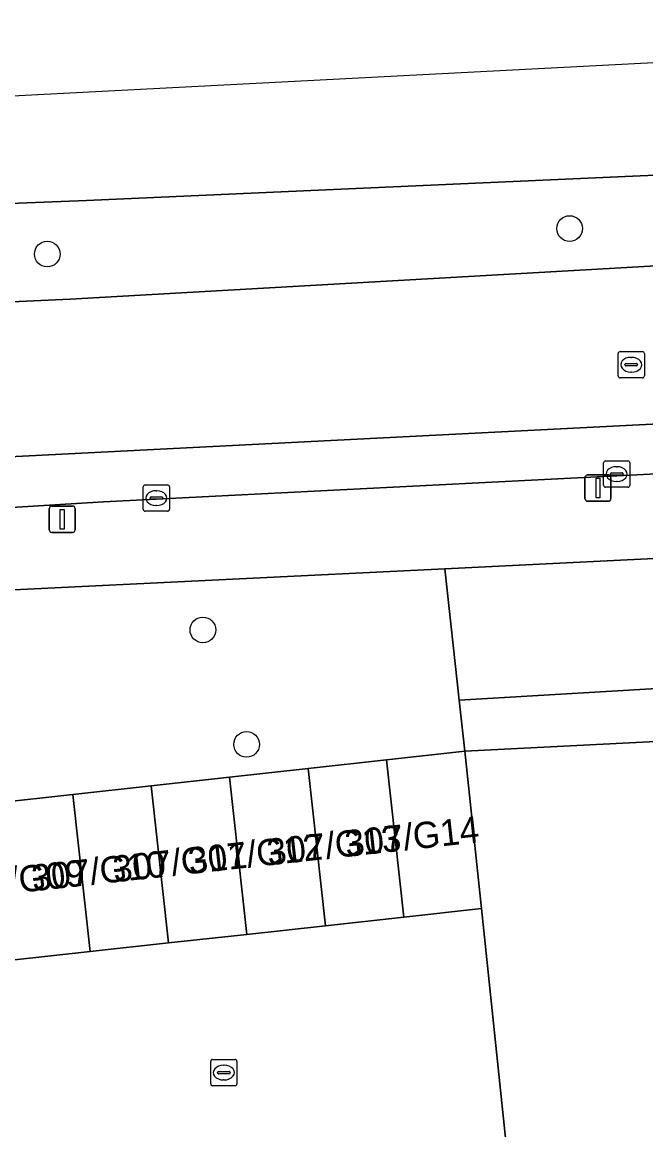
# Model space of a CAD drawing. Extents: x 161248 to 161848, y 384871 to 385383.
# Drawn here: x 161322.33 to 161346.09, y 385315.39 to 385357.57 of the extents above; entities that cross this region are included whole.
import ezdxf

# ---------------------------------------------------------------- set-up
doc = ezdxf.new("R2010")
doc.units = 0
for name, color, linetype in [('IMGEO_Berm_groen', 7, 'Continuous'), ('IMGEO_Boom', 7, 'Continuous'), ('IMGEO_Erf', 7, 'Continuous'), ('IMGEO_Groenvoorziening', 7, 'Continuous'), ('IMGEO_Kolk', 7, 'Continuous'), ('IMGEO_Lichtmast', 7, 'Continuous'), ('IMGEO_Pand', 7, 'Continuous'), ('IMGEO_Pand_nummerreeks', 7, 'Continuous'), ('IMGEO_Rijbaan_lokaal_gesloten', 7, 'Continuous'), ('IMGEO_Rijbaan_lokaal_open', 7, 'Continuous'), ('IMGEO_Rioolput', 7, 'Continuous'), ('IMGEO_Voetpad_open', 7, 'Continuous')]:
    doc.layers.add(name, color=color, linetype=linetype)

msp = doc.modelspace()

# ---------------------------------------------------------------- linework, layer by layer
at = {"layer": 'IMGEO_Berm_groen'}
for points in [[(161268.516, 385344.454), (161288.559, 385345.391), (161324.155, 385347.024), (161376.6, 385350.004), (161376.38, 385354.718), (161376.236, 385357.567), (161370.581, 385357.274)], [(161358.872, 385352.316), (161355.845, 385352.165), (161324.775, 385350.775), (161310.535, 385350.215), (161285.7, 385348.87), (161268.134, 385347.902)]]:
    msp.add_lwpolyline(points, dxfattribs=at)
at = {"layer": 'IMGEO_Boom'}
for centre in [(161343.184, 385349.709), (161323.285, 385348.736), (161329.214, 385334.424), (161330.878, 385330.066)]:
    msp.add_circle(centre, 0.489, dxfattribs=at)
at = {"layer": 'IMGEO_Erf'}
msp.add_lwpolyline([(161363.214, 385333.159), (161361.151, 385333.056), (161338.98, 385331.746), (161339.195, 385329.807), (161363.523, 385331.042), (161363.758, 385326.266), (161365.156, 385326.33), (161365.668, 385316.057), (161364.248, 385315.991)], dxfattribs=at)
at = {"layer": 'IMGEO_Groenvoorziening'}
msp.add_lwpolyline([(161377.566, 385338.678), (161338.425, 385336.75), (161338.98, 385331.746), (161361.151, 385333.056), (161363.214, 385333.159), (161369.13, 385333.454), (161375.009, 385333.746), (161381.942, 385316.048), (161382.867, 385316.429)], close=True, dxfattribs=at)
for points in [[(161338.98, 385331.746), (161338.425, 385336.75), (161321.75, 385335.94), (161313.981, 385335.418), (161306.636, 385334.858)], [(161298.371, 385333.539), (161286.821, 385329.479), (161288.275, 385308.207), (161294.324, 385308.738), (161298.104, 385309.138), (161297.027, 385319.113), (161298.021, 385319.222), (161297.365, 385325.195), (161300.353, 385325.524), (161303.341, 385325.854), (161306.329, 385326.183), (161309.316, 385326.513), (161312.304, 385326.842), (161315.292, 385327.172), (161318.28, 385327.501), (161321.268, 385327.83), (161324.256, 385328.16), (161327.244, 385328.489), (161330.231, 385328.819), (161333.219, 385329.148), (161336.207, 385329.478), (161339.195, 385329.807), (161338.98, 385331.746)]]:
    msp.add_lwpolyline(points, dxfattribs=at)
at = {"layer": 'IMGEO_Kolk'}
for p, q in [((161344.478, 385339.934), (161344.478, 385340.786)), ((161344.553, 385340.86), (161345.405, 385340.86)), ((161344.966, 385340.64), (161344.991, 385340.64)), ((161345.479, 385340.786), (161345.479, 385339.934)), ((161344.737, 385340.354), (161344.737, 385340.366)), ((161345.175, 385340.317), (161344.777, 385340.317)), ((161344.78, 385340.403), (161345.178, 385340.403)), ((161345.221, 385340.366), (161345.221, 385340.354)), ((161326.941, 385339.018), (161326.941, 385339.87)), ((161327.016, 385339.944), (161327.868, 385339.944)), ((161327.429, 385339.724), (161327.454, 385339.724)), ((161327.942, 385339.87), (161327.942, 385339.018)), ((161345.405, 385339.86), (161344.553, 385339.86)), ((161344.989, 385340.08), (161344.964, 385340.08)), ((161327.2, 385339.438), (161327.2, 385339.45)), ((161327.638, 385339.401), (161327.24, 385339.401)), ((161327.243, 385339.487), (161327.641, 385339.487)), ((161327.684, 385339.45), (161327.684, 385339.438)), ((161327.868, 385338.944), (161327.016, 385338.944)), ((161327.452, 385339.164), (161327.427, 385339.164)), ((161329.511, 385317.142), (161329.511, 385317.994)), ((161329.586, 385318.068), (161330.438, 385318.068)), ((161329.999, 385317.848), (161330.024, 385317.848)), ((161330.512, 385317.994), (161330.512, 385317.142)), ((161329.77, 385317.562), (161329.77, 385317.574)), ((161330.208, 385317.525), (161329.81, 385317.525)), ((161329.813, 385317.611), (161330.211, 385317.611)), ((161330.254, 385317.574), (161330.254, 385317.562)), ((161330.438, 385317.068), (161329.586, 385317.068)), ((161330.022, 385317.288), (161329.997, 385317.288))]:
    msp.add_line(p, q, dxfattribs=at)
for points in [[(161344.478, 385339.934), (161344.478, 385340.786)], [(161344.553, 385340.86), (161345.405, 385340.86)], [(161345.479, 385340.786), (161345.479, 385339.934)], [(161326.941, 385339.018), (161326.941, 385339.87)], [(161327.016, 385339.944), (161327.868, 385339.944)], [(161327.942, 385339.87), (161327.942, 385339.018)], [(161345.405, 385339.86), (161344.553, 385339.86)], [(161327.868, 385338.944), (161327.016, 385338.944)], [(161329.511, 385317.142), (161329.511, 385317.994)], [(161329.586, 385318.068), (161330.438, 385318.068)], [(161330.512, 385317.994), (161330.512, 385317.142)], [(161330.438, 385317.068), (161329.586, 385317.068)]]:
    msp.add_lwpolyline(points, dxfattribs=at)
for centre, radius, start, end in [((161344.555, 385340.784), 0.0765, 91.552, 178.448), ((161344.555, 385340.784), 0.0765, 91.552, 178.448), ((161345.403, 385340.784), 0.0765, 1.552, 88.448), ((161345.403, 385340.784), 0.0765, 1.552, 88.448), ((161344.777, 385340.363), 0.0403, 85.8775, 175.7526), ((161344.774, 385340.353), 0.0366, 178.938, 274.7102), ((161345.178, 385340.36), 0.043, 264.8664, 352.4533), ((161345.182, 385340.365), 0.0386, 1.7309, 96.639), ((161327.018, 385339.868), 0.0765, 91.552, 178.448), ((161327.018, 385339.868), 0.0765, 91.552, 178.448), ((161327.866, 385339.868), 0.0765, 1.552, 88.448), ((161327.866, 385339.868), 0.0765, 1.552, 88.448), ((161344.555, 385339.936), 0.0765, 181.552, 268.448), ((161344.555, 385339.936), 0.0765, 181.552, 268.448), ((161345.403, 385339.936), 0.0765, 271.552, 358.448), ((161345.403, 385339.936), 0.0765, 271.552, 358.448), ((161327.24, 385339.447), 0.0403, 85.8775, 175.7526), ((161327.237, 385339.437), 0.0366, 178.938, 274.7102), ((161327.641, 385339.444), 0.043, 264.8664, 352.4533), ((161327.645, 385339.449), 0.0386, 1.7309, 96.639), ((161327.018, 385339.02), 0.0765, 181.552, 268.448), ((161327.018, 385339.02), 0.0765, 181.552, 268.448), ((161327.866, 385339.02), 0.0765, 271.552, 358.448), ((161327.866, 385339.02), 0.0765, 271.552, 358.448), ((161329.588, 385317.992), 0.0765, 91.552, 178.448), ((161329.588, 385317.992), 0.0765, 91.552, 178.448), ((161330.436, 385317.992), 0.0765, 1.552, 88.448), ((161330.436, 385317.992), 0.0765, 1.552, 88.448), ((161329.81, 385317.571), 0.0403, 85.8775, 175.7526), ((161329.807, 385317.561), 0.0366, 178.938, 274.7102), ((161330.211, 385317.568), 0.043, 264.8664, 352.4533), ((161330.215, 385317.573), 0.0386, 1.7309, 96.639), ((161329.588, 385317.144), 0.0765, 181.552, 268.448), ((161329.588, 385317.144), 0.0765, 181.552, 268.448), ((161330.436, 385317.144), 0.0765, 271.552, 358.448), ((161330.436, 385317.144), 0.0765, 271.552, 358.448)]:
    msp.add_arc(centre, radius, start, end, dxfattribs=at)
for centre, major_axis, ratio, start_param, end_param in [((161344.965, 385340.36), (-0.387, 0.002), 0.722429, 4.712389, 7.853982), ((161344.99, 385340.36), (-0.39, 0.002), 0.717154, 1.570796, 4.712389), ((161327.428, 385339.444), (-0.387, 0.002), 0.722429, 4.712389, 7.853982), ((161327.453, 385339.444), (-0.39, 0.002), 0.717154, 1.570796, 4.712389), ((161329.998, 385317.568), (-0.387, 0.002), 0.722429, 4.712389, 7.853982), ((161330.023, 385317.568), (-0.39, 0.002), 0.717154, 1.570796, 4.712389)]:
    msp.add_ellipse(centre, major_axis=major_axis, ratio=ratio, start_param=start_param, end_param=end_param, dxfattribs=at)
at = {"layer": 'IMGEO_Lichtmast'}
for p, q in [((161343.769, 385339.425), (161343.769, 385340.225)), ((161343.769, 385340.225), (161343.769, 385339.425)), ((161343.869, 385340.325), (161344.659, 385340.325)), ((161344.659, 385340.325), (161343.869, 385340.325)), ((161344.759, 385340.225), (161344.759, 385339.425)), ((161344.759, 385339.425), (161344.759, 385340.225)), ((161344.659, 385339.325), (161343.869, 385339.325)), ((161343.869, 385339.325), (161344.659, 385339.325)), ((161323.358, 385338.24), (161323.358, 385339.04)), ((161323.358, 385339.04), (161323.358, 385338.24)), ((161323.458, 385339.14), (161324.248, 385339.14)), ((161324.248, 385339.14), (161323.458, 385339.14)), ((161324.348, 385339.04), (161324.348, 385338.24)), ((161324.348, 385338.24), (161324.348, 385339.04)), ((161324.248, 385338.14), (161323.458, 385338.14)), ((161323.458, 385338.14), (161324.248, 385338.14))]:
    msp.add_line(p, q, dxfattribs=at)
for points in [[(161344.189, 385340.2), (161344.339, 385340.2), (161344.339, 385339.45), (161344.189, 385339.45), (161344.189, 385340.2)], [(161323.778, 385339.015), (161323.928, 385339.015), (161323.928, 385338.265), (161323.778, 385338.265), (161323.778, 385339.015)]]:
    msp.add_lwpolyline(points, dxfattribs=at)
for centre, start, end in [((161343.869, 385340.225), 90, 180), ((161343.869, 385340.225), 90, 180), ((161344.659, 385340.225), 0, 90), ((161344.659, 385340.225), 360, 90), ((161343.869, 385339.425), 180, 270), ((161343.869, 385339.425), 180, 270), ((161344.659, 385339.425), 270, 0), ((161344.659, 385339.425), 270, 0), ((161323.458, 385339.04), 90, 180), ((161323.458, 385339.04), 90, 180), ((161324.248, 385339.04), 0, 90), ((161324.248, 385339.04), 360, 90), ((161323.458, 385338.24), 180, 270), ((161323.458, 385338.24), 180, 270), ((161324.248, 385338.24), 270, 0), ((161324.248, 385338.24), 270, 0)]:
    msp.add_arc(centre, 0.1, start, end, dxfattribs=at)
at = {"layer": 'IMGEO_Pand'}
msp.add_lwpolyline([(161364.248, 385315.991), (161365.668, 385316.057), (161365.156, 385326.33), (161363.758, 385326.266), (161363.523, 385331.042), (161339.195, 385329.807), (161339.824, 385323.814), (161340.871, 385313.86), (161341.506, 385307.829), (161341.943, 385303.675), (161353.329, 385308.005), (161353.721, 385306.981), (161357.263, 385308.334), (161357.21, 385308.445), (161359.113, 385309.131), (161359.136, 385309.338)], dxfattribs=at)
for points in [[(161336.867, 385323.489), (161339.824, 385323.814), (161339.195, 385329.807), (161336.207, 385329.478)], [(161333.219, 385329.148), (161330.231, 385328.819), (161330.891, 385322.833), (161333.879, 385323.161)], [(161333.879, 385323.161), (161336.867, 385323.489), (161336.207, 385329.478), (161333.219, 385329.148)], [(161330.231, 385328.819), (161327.244, 385328.489), (161327.903, 385322.505), (161330.891, 385322.833)], [(161327.244, 385328.489), (161324.256, 385328.16), (161324.915, 385322.176), (161327.903, 385322.505)], [(161321.927, 385321.848), (161324.915, 385322.176), (161324.256, 385328.16), (161321.268, 385327.83)]]:
    msp.add_lwpolyline(points, close=True, dxfattribs=at)
at = {"layer": 'IMGEO_Rijbaan_lokaal_gesloten'}
for points in [[(161363.136, 385353.342), (161370.581, 385357.274), (161310.703, 385354.168), (161252.644, 385354.672)], [(161382.607, 385342.195), (161401.421, 385343.184), (161500, 385348.169), (161538.421, 385350.118), (161631.519, 385354.842), (161631.397, 385356.891), (161617.266, 385356.241), (161538.32, 385351.908), (161405.743, 385345.272), (161403.061, 385345.136), (161313.081, 385340.569), (161302.699, 385339.685), (161293.531, 385337.916), (161290.897, 385337.069), (161291.775, 385334.722), (161292.828, 385335.119)], [(161254.106, 385347.204), (161261.578, 385347.58), (161261.808, 385347.59), (161264.882, 385347.731), (161268.134, 385347.902), (161285.7, 385348.87), (161310.535, 385350.215), (161324.775, 385350.775), (161355.845, 385352.165), (161358.872, 385352.316)], [(161290.897, 385337.069), (161293.531, 385337.916), (161302.699, 385339.685), (161313.081, 385340.569), (161403.061, 385345.136), (161402.887, 385348.241), (161402.713, 385351.347)], [(161381.89, 385350.269), (161380.733, 385350.21), (161376.6, 385350.004), (161324.155, 385347.024), (161288.559, 385345.391), (161268.516, 385344.454), (161266.956, 385344.394), (161265.291, 385344.323), (161262.15, 385344.152), (161258.577, 385343.968), (161255.028, 385343.811), (161254.449, 385343.782)], [(161304.085, 385337.824), (161305.471, 385337.988), (161309.803, 385338.304), (161313.29, 385338.586), (161317.381, 385338.812), (161325.423, 385339.298), (161382.607, 385342.195)]]:
    msp.add_lwpolyline(points, dxfattribs=at)
at = {"layer": 'IMGEO_Rijbaan_lokaal_open'}
msp.add_lwpolyline([(161340.871, 385313.86), (161339.824, 385323.814), (161336.867, 385323.489), (161333.879, 385323.161), (161330.891, 385322.833), (161327.903, 385322.505), (161324.915, 385322.176), (161321.927, 385321.848), (161318.939, 385321.52), (161315.951, 385321.192), (161312.963, 385320.863), (161309.975, 385320.535), (161306.987, 385320.207), (161304, 385319.879), (161301.012, 385319.551), (161298.021, 385319.222), (161298.846, 385311.258)], dxfattribs=at)
at = {"layer": 'IMGEO_Rioolput'}
for p, q in [((161345.032, 385344.098), (161345.032, 385344.95)), ((161345.107, 385345.024), (161345.959, 385345.024)), ((161345.52, 385344.804), (161345.545, 385344.804)), ((161346.033, 385344.95), (161346.033, 385344.098)), ((161345.291, 385344.518), (161345.291, 385344.53)), ((161345.729, 385344.481), (161345.331, 385344.481)), ((161345.334, 385344.567), (161345.732, 385344.567)), ((161345.775, 385344.53), (161345.775, 385344.518)), ((161345.959, 385344.024), (161345.107, 385344.024)), ((161345.543, 385344.244), (161345.518, 385344.244))]:
    msp.add_line(p, q, dxfattribs=at)
for points in [[(161345.032, 385344.098), (161345.032, 385344.95)], [(161345.107, 385345.024), (161345.959, 385345.024)], [(161346.033, 385344.95), (161346.033, 385344.098)], [(161345.959, 385344.024), (161345.107, 385344.024)]]:
    msp.add_lwpolyline(points, dxfattribs=at)
for centre, radius, start, end in [((161345.109, 385344.948), 0.0765, 91.552, 178.448), ((161345.109, 385344.948), 0.0765, 91.552, 178.448), ((161345.957, 385344.948), 0.0765, 1.552, 88.448), ((161345.957, 385344.948), 0.0765, 1.552, 88.448), ((161345.331, 385344.527), 0.0403, 85.8775, 175.7526), ((161345.328, 385344.517), 0.0366, 178.938, 274.7102), ((161345.732, 385344.524), 0.043, 264.8664, 352.4533), ((161345.736, 385344.529), 0.0386, 1.7309, 96.639), ((161345.109, 385344.1), 0.0765, 181.552, 268.448), ((161345.109, 385344.1), 0.0765, 181.552, 268.448), ((161345.957, 385344.1), 0.0765, 271.552, 358.448), ((161345.957, 385344.1), 0.0765, 271.552, 358.448)]:
    msp.add_arc(centre, radius, start, end, dxfattribs=at)
for centre, major_axis, ratio, start_param, end_param in [((161345.519, 385344.524), (-0.387, 0.002), 0.722429, 4.712389, 7.853982), ((161345.544, 385344.524), (-0.39, 0.002), 0.717154, 1.570796, 4.712389)]:
    msp.add_ellipse(centre, major_axis=major_axis, ratio=ratio, start_param=start_param, end_param=end_param, dxfattribs=at)
at = {"layer": 'IMGEO_Voetpad_open'}
for points in [[(161382.607, 385342.195), (161325.423, 385339.298), (161317.381, 385338.812), (161313.29, 385338.586), (161309.803, 385338.304), (161305.471, 385337.988), (161304.085, 385337.824)], [(161306.636, 385334.858), (161313.981, 385335.418), (161321.75, 385335.94), (161338.425, 385336.75), (161377.566, 385338.678), (161383.037, 385338.948)]]:
    msp.add_lwpolyline(points, dxfattribs=at)

# ---------------------------------------------------------------- texts
at = {"layer": 'IMGEO_Pand_nummerreeks'}
for s, p in [('307/G14', (161334.68, 385325.784)), ('307/G12', (161328.713, 385325.129)), ('307/G13', (161331.708, 385325.458)), ('307/G11', (161325.841, 385324.813)), ('307/G10', (161322.747, 385324.473)), ('307/G09', (161319.662, 385324.134))]:
    msp.add_text(s, height=1, rotation=6.2687, dxfattribs=at).set_placement(p)

doc.saveas('drawing.dxf')
